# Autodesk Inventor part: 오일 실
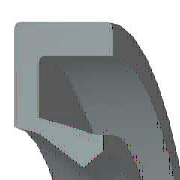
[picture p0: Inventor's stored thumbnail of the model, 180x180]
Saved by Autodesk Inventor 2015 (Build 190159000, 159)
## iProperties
IsCustomPart: 1
Created: 2012-02
Part Number: 오일 실
Material: 고무
Description: 오일 실 - 스프링 장착, 비스프링, 고무 덮개 G
Document SubType Name: Modeling
Standard: JIS B 2402
Designer: mduedu
Standards Organization: JIS
Language: ko-KR
Size Designation: 20 32 5 A
Categories: <MemberInstance><Categories><Category DisplayName="샤프트 부품" InternalName="7f7aeb1f-a693-4053-b835-cee3144e0d98" Mnemonic="SHFT"><Category DisplayName="실링" Intern
Density: 0.93 g/cm^3
Appearance: 고무 - 검은색 - 버전 1.1
Author: mduedu
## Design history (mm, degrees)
body "Solid1"
revolve "회전1" stored, may be unused: angle "d29" = 360 deg
chamfer "모따기1" distance "d30" = 0.25 (= 0.05 x b); stored, may be unused: second distance "d31" = 0.5 (= 0.1 x b), angle "d39" = 45 deg
chamfer "모따기2" distance "d32" = 0.5 (= 0.1 x b); stored, may be unused: second distance "d33" = 0.25 (= 0.05 x b), angle "d40" = 45 deg
fillet "모깎기1" dims "d34" = 0.25 (= 0.05 x b)
sketch "스케치2"
  geometry: L1 (10.997, -3.438)-(11.297, -5); L2 (10.597, -3.282)-(10.997, -3.438); L3 (10, -1.72)-(10.597, -3.282); L4 (11.091, -1.22)-(10, -1.72); L5 (12.133, -3.75)-(11.091, -1.22); L6 (13.333, -3.75)-(12.133, -3.75); L7 (14.667, -1.25)-(13.333, -3.75); L8 (14.667, 0)-(14.667, -1.25); L9 (16, 0)-(14.667, 0); L10 (16, -5)-(16, 0); L11 (11.297, -5)-(16, -5); L12 (0, -9.6)-(0, 1.6) reference; L13 (28, 0)-(14, 0) reference
  constraints: 22 end point, 3 horizontal, 2 vertical
  dimensions: "d2" = 5 distance of L10.start L9.start (= b); "d4" = 1.25 vertical distance of L5.start L1.end (= 0.25 x b); "d6" = 1.33333 distance of L9.start L8.start (= 0.111111 x dd - 0.111111 x Diam); "d8" = 1.25 distance of L8.start L7.start (= 0.25 x b); "d10" = 1.33333 horizontal distance of L7.start L6.start (= 0.111111 x dd - 0.111111 x Diam); "d12" = 1.21951 vertical distance of L9.start L4.start (= 0.243902 x b); "d14" = 1.09091 horizontal distance of L4.start L3.start (= 0.0909091 x dd - 0.0909091 x Diam); "d16" = 0.5 vertical distance of L4.start L3.start (= 0.1 x b); "d18" = 1.2 distance of L6.start L5.start (= 0.1 x dd - 0.1 x Diam); "d20" = 1.5625 vertical distance of L3.start L2.start (= 0.3125 x b); "d22" = 0.59701 horizontal distance of L3.start L2.start (= 0.0497512 x dd - 0.0497512 x Diam); "d24" = 0.3 horizontal distance of L1.start L1.end (= 0.025 x dd - 0.025 x Diam); "d26" = 1.5625 vertical distance of L1.start L1.end (= 0.3125 x b); "d28" = 0.4 horizontal distance of L2.start L1.start (= 0.0333333 x dd - 0.0333333 x Diam); "d35" = 0 distance between parallel lines of L13 L9; "d36" = 16 distance between parallel lines of L12 L10 (= 0.5 x dd); "d37" = 10 distance from line of L12 L3.start (= 0.5 x Diam)
other parameters: "dd" = 32 [user parameter; used in 8 equation terms], "b" = 5 [user parameter; used in 12 equation terms], "d1" = 8 (derived), "d3" = 2 (derived), "d5" = 2.22222 (derived), "d7" = 2 (derived), "d9" = 2.22222 (derived), "d11" = 1.95122 (derived), "d13" = 1.81818 (derived), "d15" = 0.8 (derived), "d17" = 2 (derived), "d19" = 2.5 (derived), "d21" = 0.99502 (derived), "d23" = 0.5 (derived), "d25" = 2.5 (derived), "d27" = 0.66667 (derived), "d38" = 0
